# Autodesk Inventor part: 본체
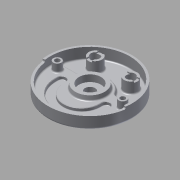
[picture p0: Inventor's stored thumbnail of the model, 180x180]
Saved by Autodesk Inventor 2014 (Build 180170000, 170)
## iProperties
Created: 2015-06
Part Number: 본체
Material: 알루미늄 6061
Document SubType Name: Modeling
Designer: MYHOME
Mass: 1064.51 g
Surface Area: 1032.34 cm^2
Volume: 392.807 cm^3
Density: 2.71 g/cm^3
Appearance: 알루미늄 - 평지
Author: MYHOME
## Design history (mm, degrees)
sketch "스케치1"
  geometry: C1 r 95 at (0, 0); C2 r 90 at (0, 0); 1 further point
  constraints: 2 centre point, 2 coincident
  dimensions: "d0" = 190 diameter of C1; "d1" = 180 diameter of C2
extrude "돌출1" new body sketch "스케치1" distance "d2" = 32; taper "d3" = 0 deg
extrude "돌출2" join sketch "스케치1" distance "d4" = 7; taper "d5" = 0 deg
sketch "스케치2"
  geometry: L1 (-88.566, 16)-(-38.833, 16); L2 (38.833, 16)-(88.566, 16); A1 r 90 centre (0, 0) between (-88.566, 16) and (88.566, 16) reference; A2 r 42 centre (0, 0) between (38.833, 16) and (-38.833, 16)
  constraints: 4 end point, 4 point on circle, 1 centre point, 1 coincident, 1 collinear, 1 horizontal
  dimensions: "d7" = 84 diameter of A2; "d8" = 16 distance from line of L2 A2.centre; "d9" = 16 distance from line of A1.centre L1
extrude "돌출3" join sketch "스케치2" distance "d10" = 7; taper "d11" = 0 deg
fillet "모깎기1" dims "d12" = 10
sketch "스케치3"
  geometry: C1 r 15 at (-40, 52); C2 r 15 at (40, 52); A1 r 90 centre (0, 0) between (85.114, 29.25) and (-85.114, 29.25) reference
  constraints: 2 centre point, 1 horizontal alignment
  dimensions: "d13" = 30 diameter of C1; "d14" = 30 diameter of C2; "d15" = 80 distance of C2.centre C1.centre; "d16" = 40 horizontal distance of A1.centre C2.centre; "d17" = 52 vertical distance of A1.centre C2.centre
extrude "돌출4" join sketch "스케치3" distance "d18" = 25; taper "d19" = 0 deg
sketch "스케치4"
  geometry: C1 r 15 at (0, 0) reference; C2 r 15 at (80, 0) reference; C3 r 10 at (80, 0); C4 r 10 at (0, 0); 1 further point
  constraints: 2 centre point, 2 coincident
  dimensions: "d20" = 20 diameter of C3; "d21" = 20 diameter of C4
extrude "돌출5" cut sketch "스케치4" stored distance "d22" = 25; taper "d23" = 0 deg
sketch "스케치5"
  geometry: L1 (6, -15)-(-6, -15); L2 (-6, -15)-(-6, 15); L3 (-6, 15)-(6, 15); L4 (6, 15)-(6, -15); L5 (6, -15)-(-6, 15); L6 (-6, -15)-(6, 15); L7 (95, -6)-(65, -6); L8 (65, -6)-(65, 6); L9 (65, 6)-(95, 6); L10 (95, 6)-(95, -6); L11 (95, -6)-(65, 6); L12 (65, -6)-(95, 6); C1 r 10 at (80, 0) reference; 5 further points
  constraints: 24 end point, 6 midpoint, 4 parallel, 2 horizontal, 2 perpendicular, 1 horizontal alignment, 1 vertical alignment, 2 other
  dimensions: "d24" = 12 distance between parallel lines of L7 L9; "d25" = 12 distance between parallel lines of L4 L2
extrude "돌출6" cut sketch "스케치5" distance "d26" = 3; taper "d27" = 0 deg
sketch "스케치6"
  geometry: L1 (-45.033, 16)-(-75.657, 16) reference; L2 (-59, -19)-(-41, -19); L3 (41, -19)-(59, -19); L4 (50, -19)-(50, -14); L5 (41, -19)-(41, -14); L6 (59, -19)-(59, -14); L7 (-50, -19)-(-50, -14); L8 (-41, -19)-(-41, -14); L9 (-59, -19)-(-59, -14); A1 r 90 centre (0, 0) between (-85.114, 29.25) and (85.114, 29.25) reference; A2 r 50 centre (0, -19) between (-50, -19) and (50, -19); A3 r 59 centre (0, -19) between (-59, -19) and (59, -19); A4 r 41 centre (0, -19) between (-41, -19) and (41, -19); A5 r 9 centre (-50, -19) between (-41, -19) and (-59, -19); A6 r 9 centre (50, -19) between (59, -19) and (41, -19); A7 r 9 centre (50, -14) between (41, -14) and (59, -14); A8 r 9 centre (-50, -14) between (-41, -14) and (-59, -14)
  constraints: 16 end point, 14 point on circle, 10 tangent, 7 centre point, 4 horizontal alignment, 2 coincident, 1 collinear, 1 midpoint, 1 parallel, 1 perpendicular, 1 vertical alignment
  dimensions: "d28" = 19 distance of A1.centre A2.centre; "d29" = 59 radius of A3; "d30" = 41 radius of A4; "d41" = 5 distance of L4.start L4.end; "d42" = 18 diameter of A7; "d44" = 5 distance of L7.start L7.end; "d45" = 18 diameter of A8
extrude "돌출7" cut sketch "스케치6" distance "d46" = 7; taper "d47" = 0 deg
chamfer "모따기1" distance "d48" = 1; stored, may be unused: second distance "d49" = 2, angle "d50" = 45 deg
fillet "모깎기2" dims "d51" = 1
sketch "스케치7"
  geometry: C1 r 35 at (0, 0); A1 r 42 centre (0, 0) between (36.373, 21) and (-36.373, 21) reference
  constraints: 1 centre point, 1 coincident
  dimensions: "d52" = 70 diameter of C1
extrude "돌출8" join sketch "스케치7" distance "d53" = 10; taper "d54" = -10 deg
fillet "모깎기3" dims "d55" = 3
sketch "스케치8"
  geometry: C1 r 9 at (-74, 0); C2 r 9 at (74, 0); A1 r 90 centre (0, 0) between (-85.114, 29.25) and (85.114, 29.25) reference
  constraints: 2 centre point, 2 horizontal alignment
  dimensions: "d69" = 18 diameter of C1; "d70" = 18 diameter of C2; "d71" = 148 distance of C2.centre C1.centre; "d72" = 74 distance of A1.centre C2.centre
extrude "돌출9" join sketch "스케치8" stored distance "d73" = 10; taper "d74" = 0 deg
fillet "모깎기5" dims "d75" = 3
sketch "스케치9"
  geometry: C1 r 9 at (74, 0) reference
hole "구멍2" sketch "스케치9" at (74, 0) diameter "d76" = 11; stored, may be unused: countersink angle "d80" = 90 deg, drill point angle "d82" = 118 deg; dims "d77" = 6, "d78" = 18, "d79" = 11, "d81" = 8
sketch "스케치10"
  geometry: C1 r 9 at (-74, 0) reference
hole "구멍3" sketch "스케치10" at (-74, 0) diameter "d83" = 11; stored, may be unused: countersink angle "d87" = 90 deg, drill point angle "d89" = 118 deg; dims "d84" = 6, "d85" = 18, "d86" = 11, "d88" = 8
fillet "모깎기7" dims "d95" = 3
fillet "모깎기8" dims "d96" = 5
fillet "모깎기9" dims "d97" = 3
sketch "스케치13"
  geometry: C1 r 90 at (0, 0) reference; A1 r 68 centre (0, 0) between (0, -68) and (68, 0)
  constraints: 2 point on circle, 1 centre point, 1 coincident, 1 other
  dimensions: "d100" = 68 radius of A1
feature "엠보싱1" sketch "스케치13" dims "d1" = 180, "d101" = 0.5, "d102" = 0
fillet "모깎기10" dims "d111" = 3
sketch "스케치17"
  geometry: C1 r 90 at (0, 0) reference; C2 r 26 at (0, 0)
  constraints: 1 centre point, 1 coincident
  dimensions: "d115" = 52 diameter of C2
extrude "돌출14" join sketch "스케치17" distance "d116" = 10; taper "d117" = -15 deg
hole "구멍4" diameter "d120" = 23; stored, may be unused: countersink angle "d124" = 90 deg, drill point angle "d126" = 118 deg; dims "d118" = 10, "d119" = 10, "d121" = 6, "d122" = 50, "d123" = 15, "d125" = 8
fillet "모깎기11" dims "d127" = 3
sketch "스케치20"
  geometry: L1 (0, 0)-(-94.075, -13.221); L2 (0, 0)-(94.075, -13.221); L3 (-95, 0)-(95, 0); A1 r 90 centre (0, 0) between (-89.124, -12.526) and (89.124, -12.526) reference; A2 r 95 centre (0, 0) between (-94.075, -13.221) and (94.075, -13.221) reference; 2 further points
  constraints: 6 end point, 6 point on circle, 2 coincident, 2 point on line, 1 horizontal, 1 midpoint
  dimensions: "d128" = 8 deg angle of L2 L3; "d129" = 8 deg angle of L3 L1
extrude "돌출15" cut sketch "스케치20" distance "d130" = 5; taper "d131" = 0 deg
fillet "모깎기12" dims "d132" = 3
chamfer "모따기4" distance "d133" = 1; stored, may be unused: second distance "d134" = 2, angle "d135" = 45 deg
node "솔리드1"
node "투영된 루프1"
node "투영된 루프2"
node "투영된 루프3"
node "투영된 루프4"
other parameters: "d99" = 136
